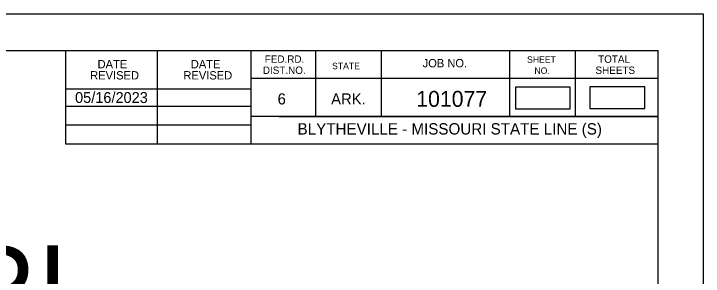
# Model space of a CAD drawing. Extents: x 1366406 to 1373462, y 376856 to 381998.
# Drawn here: x 1370296 to 1371025, y 380996 to 381273 of the extents above; entities that cross this region are included whole.
import ezdxf

# ---------------------------------------------------------------- set-up
doc = ezdxf.new("R2010")
doc.units = 0
for name, color, linetype in [('R_Border', 7, 'Continuous'), ('R_Border Notes', 7, 'Continuous'), ('R_Draft', 7, 'Continuous'), ('R_No Plot', 7, 'Continuous'), ('R_Revision Date Text', 7, 'Continuous')]:
    doc.layers.add(name, color=color, linetype=linetype)

msp = doc.modelspace()

# ---------------------------------------------------------------- linework, layer by layer
at = {"layer": 'R_Border'}
for p, q in [((1367815.86, 381233.92), (1370977.66, 381233.92)), ((1370351.26, 381135.12), (1370351.26, 381233.92)), ((1370448.06, 381135.12), (1370448.06, 381233.92)), ((1370546.66, 381233.92), (1370546.66, 381135.12)), ((1370615.06, 381233.92), (1370615.06, 381164.52)), ((1370684.46, 381233.92), (1370684.46, 381164.52)), ((1370820.26, 381233.92), (1370820.26, 381164.52)), ((1370889.66, 381233.92), (1370889.66, 381164.52)), ((1370977.66, 379179.32), (1370977.66, 381233.92)), ((1370977.66, 381204.52), (1370546.66, 381204.52)), ((1370977.66, 381204.72), (1370977.66, 381204.72)), ((1370351.26, 381193.72), (1370546.66, 381193.72)), ((1370351.26, 381175.12), (1370546.66, 381175.12)), ((1370977.66, 381164.52), (1370546.66, 381164.52)), ((1370576.26, 381164.52), (1370977.66, 381164.52)), ((1370351.26, 381155.72), (1370546.66, 381155.72)), ((1370977.66, 381135.12), (1370351.26, 381135.12))]:
    msp.add_line(p, q, dxfattribs=at)
for points in [[(1370826.55, 381172.49), (1370884.55, 381172.49), (1370884.55, 381195.46), (1370826.55, 381195.46)], [(1370905.32, 381172.89), (1370963.32, 381172.89), (1370963.32, 381195.86), (1370905.32, 381195.86)]]:
    msp.add_lwpolyline(points, close=True, dxfattribs=at)
at = {"layer": 'R_No Plot'}
msp.add_line((1367691.85, 381272.86), (1371025.18, 381272.86), dxfattribs=at)
msp.add_lwpolyline([(1367691.79, 381272.86), (1371025.18, 381272.86), (1371025.18, 379139.49), (1367691.79, 379139.49)], close=True, dxfattribs=at)

# ---------------------------------------------------------------- texts
at = {"layer": 'R_Border'}
for s, height, p in [('DATE', 8.792, (1370384.64, 381215.28)), ('DATE', 8.792, (1370483.24, 381215.28)), ('FED.RD.', 7.819, (1370561.46, 381221.12)), ('JOB NO.', 8.792, (1370728.46, 381216.32)), ('SHEET', 6.84, (1370838.86, 381221.12)), ('TOTAL', 7.819, (1370914.06, 381221.12)), ('DIST.NO.', 7.819, (1370559.46, 381209.32)), ('STATE', 6.84, (1370632.66, 381214.32)), ('NO.', 6.84, (1370846.66, 381209.32)), ('SHEETS', 7.819, (1370911.26, 381209.32)), ('REVISED', 8.792, (1370376.84, 381203.48)), ('REVISED', 8.792, (1370475.44, 381203.48)), ('6', 11.72, (1370575.06, 381177.12)), ('ARK.', 11.723, (1370631.66, 381177.12))]:
    msp.add_text(s, height=height, dxfattribs=at).set_placement(p)
at = {"layer": 'R_Border Notes'}
for s, height, p in [('101077', 16.8, (1370721.71, 381174.58)), ('BLYTHEVILLE - MISSOURI STATE LINE (S)', 12, (1370596.17, 381145.31))]:
    msp.add_text(s, height=height, dxfattribs=at).set_placement(p)
at = {"layer": 'R_Draft'}
msp.add_text('BLYTHEVILLE - MISSOURI ', height=89.9998, dxfattribs=at).set_placement((1368855.73, 380938.17))
at = {"layer": 'R_Revision Date Text'}
msp.add_text('05/16/2023', height=11.5, dxfattribs=at).set_placement((1370360.83, 381178.67))

doc.saveas('drawing.dxf')
